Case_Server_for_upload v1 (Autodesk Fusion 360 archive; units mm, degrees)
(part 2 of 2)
joint_origin "JointOrigin1"
derived_base_feature "Derived Base Feature1" bodies "side1", "side2", "Body1"
position "Position11"
joint_origin "JointOrigin1"
as_built_joint "As-built9"
as_built_joint "As-built10"
position "Position12"
as_built_joint "As-built11"
base_feature "Base Feature1"
sketch "Sketch1" plane through (0, 0, 0) normal (0, 0, 1) x axis (1, 0, 0)
  line L1 (-0.425, -0.775) -> (0.425, -0.775)
  line L2 (-0.425, 0.775) -> (-0.425, -0.775)
  line L3 (0.425, 0.775) -> (-0.425, 0.775)
  line L4 (0.425, -0.775) -> (0.425, 0.775)
  line L5 (-0.425, 0) -> (0.425, 0)
  line L6 (-0.425, -0.625) -> (0.425, -0.625)
  line L7 (-0.425, 0.625) -> (0.425, 0.625)
  line L8 (0, -0.625) -> (0, 0.625)
  point P6 (0.425, 0)
  point P7 (-0.425, 0)
  point P8 (0.425, -0.625)
  point P9 (-0.425, -0.625)
  point P10 (0.425, 0.625)
  point P11 (-0.425, 0.625)
  point P12 (0, 0.625)
  point P13 (0, -0.625)
  point P1 (0, 0)
  point P2 (0.425, -0.775)
  point P3 (-0.425, -0.775)
  point P5 (0.425, 0.775)
  horizontal L1
  vertical L2
  horizontal L3
  vertical L4
  midpoint L4 P6
  midpoint L2 P7
  coincident L4 P8
  coincident L2 P9
  perpendicular L2 L6
  coincident L4 P10
  coincident L2 P11
  perpendicular L2 L7
  midpoint L7 P12
  midpoint L6 P13
  coincident P1 L5
  coincident P1 L8
  dimension "d117_1_1" distance P2 P3 = 0.85
  dimension "d118_1_1" distance P2 P5 = 1.55
  dimension "d120_1_1" distance L1 L6 = 0.15
  dimension "d121_1_1" distance L3 L7 = 0.15
extrude "Extrude1" new body sketch "Sketch1" profile of L2 L4 L6 L7 blind 0.45 named "d123_1_1"
extrude "Extrude2" new body sketch "Sketch1" profile of L1 L2 L3 L4 L6 L7 blind 0.45 named "d125_1_1" bodies "side1", "side2"
sketch "Sketch2" plane through (0, 0, 0.45) normal (0, 0, 1) x axis (1, 0, 0)
  dimension "d127_1_1" = 0.5
extrude "Extrude3" add sketch "Sketch2" blind 0.01 named "d128_1_1"
position "Position13"
joint_origin "JointOrigin2"
joint "Assemble8" alignAngle 90 alignOffsetX 6.925 (= "( 25.4 / 2 ) * 1 mm - ( 1.55 / 2 ) * 1 mm - 5 mm") alignOffsetY -6.675 (= "( -26.2 / 2 ) * 1 mm + ( 0.85 / 2 ) * 1 mm + 6 mm") alignOffsetZ 0
sketch "Sketch1" plane through (0, 0, 0) normal (0, 0, 1) x axis (1, 0, 0)
  line L1 (-0.8, -1.45) -> (0.8, -1.45)
  line L2 (-0.8, 1.45) -> (-0.8, -1.45)
  line L3 (0.8, 1.45) -> (-0.8, 1.45)
  line L4 (0.8, -1.45) -> (0.8, 1.45)
  line L5 (-0.8, 1.45) -> (0.8, -1.45)
  line L6 (0.8, 1.45) -> (-0.8, -1.45)
  point P6 (0, 0)
  point P1 (0, 0)
  point P4 (-0.8, 1.45)
  point P5 (0.8, 1.45)
  point P3 (-0.8, -1.45)
  horizontal L1
  perpendicular L1 L2
  parallel L1 L3
  parallel L2 L4
  coincident L5 P6
  coincident L6 P6
  coincident P1 P6
  dimension "d1_1" distance P4 P5 = 1.6
  dimension "d2_1" distance P3 P4 = 2.9
extrude "Extrude1" new body sketch "Sketch1" profile of L1 L2 L3 L4 along normal blind 1.1 named "d3_1"
work_plane "WorkPlane1"
sketch "Sketch2" plane through (0, 0, 0.4) normal (0, -1, 0) x axis (1, 0, 0)
  line L1 (-0.8, 0.7) -> (0.8, 0.7)
  line L2 (0.8, -0.4) -> (-0.8, -0.4)
  line L3 (0, -0.4) -> (0, 0.7)
  line L4 (-0.8, 0.7) -> (-0.8, -0.4)
  line L5 (0.8, 0.7) -> (0.8, -0.4)
  line L6 (0.8, 0.15) -> (-0.8, 0.15)
  line L7 (1.1, 0.4) -> (0.8, 0.4)
  line L8 (1.1, -0.35) -> (1.1, 0.4)
  line L9 (1.4, -0.35) -> (1.1, -0.35)
  line L10 (1.4, -0.5) -> (1.4, -0.35)
  line L11 (0.95, -0.5) -> (1.4, -0.5)
  line L12 (0.95, 0.25) -> (0.95, -0.5)
  line L13 (0.8, 0.25) -> (0.95, 0.25)
  line L14 (0.8, 0.25) -> (0.8, 0.4)
  line L15 (-0.95, -0.5) -> (-1.4, -0.5)
  line L16 (-0.8, 0.25) -> (-0.8, 0.4)
  line L17 (-1.1, 0.4) -> (-0.8, 0.4)
  line L18 (-1.4, -0.5) -> (-1.4, -0.35)
  line L19 (-1.1, -0.35) -> (-1.1, 0.4)
  line L20 (-0.8, 0.25) -> (-0.95, 0.25)
  line L21 (-1.4, -0.35) -> (-1.1, -0.35)
  line L22 (-0.95, 0.25) -> (-0.95, -0.5)
  point P6 (0, 0.7)
  point P7 (0, -0.4)
  point P10 (-0.8, 0.15)
  point P11 (0.8, 0.15)
  point P12 (0.8, 0.4)
  point P19 (0.8, 0.25)
  point P5 (0.8, -0.4)
  point P30 (-0.8, -0.4)
  point P8 (0.8, -0.4)
  point P22 (-0.8, -0.4)
  point P24 (-0.8, 0.15)
  point P26 (-0.8, 0.4)
  point P13 (1.1, 0.4)
  point P20 (-1.1, 0.4)
  point P14 (1.1, -0.35)
  point P21 (-1.1, -0.35)
  point P15 (1.4, -0.35)
  point P25 (-1.4, -0.35)
  point P16 (1.4, -0.5)
  point P23 (-1.4, -0.5)
  point P17 (0.95, -0.5)
  point P27 (-0.95, -0.5)
  point P18 (0.95, 0.25)
  point P29 (-0.95, 0.25)
  point P28 (-0.8, 0.25)
  midpoint L1 P6
  midpoint L2 P7
  midpoint L4 P10
  midpoint L5 P11
  coincident L5 P12
  perpendicular L5 L7
  perpendicular L7 L8
  perpendicular L5 L9
  perpendicular L9 L10
  perpendicular L5 L11
  perpendicular L11 L12
  coincident L5 P19
  perpendicular L5 L13
  symmetric P5 L3 P30
  symmetric L3 P8 P22
  symmetric L3 P11 P24
  symmetric L3 P12 P26
  symmetric L3 P13 P20
  symmetric L3 P14 P21
  symmetric L3 P15 P25
  symmetric L3 P16 P23
  symmetric L3 P17 P27
  symmetric L3 P18 P29
  symmetric L3 P19 P28
  dimension "d5_1" distance L2 L11 = 0.1
  dimension "d8_2" distance P12 P19 = 0.15
  dimension "d9_2" distance L6 L13 = 0.1
  dimension "d10_2" distance L8 L12 = 0.15
  dimension "d11_2" distance P15 P16 = 0.15
  dimension "d13_1" distance L3 L10 = 1.4 (= "( 2.8 / 2 ) * 1 mm")
  dimension "d14_1" distance L8 L10 = 0.3
extrude "Extrude2" new body sketch "Sketch2" profile of L15 L16 L17 L18 L19 L20 L21 L22 distance 0.2 named "d15_1" bodies "leg1"
extrude "Extrude3" new body sketch "Sketch2" profile of L7 L8 L9 L10 L11 L12 L13 L14 distance 0.2 named "d17_1" from offset 0.95 (= "( 1.9 / 2 ) * 1 mm") named "d19_1" bodies "leg2"
extrude "Extrude4" new body sketch "Sketch2" profile of L7 L8 L9 L10 L11 L12 L13 L14 distance 0.2 named "d21_1" from offset -0.95 (= "( -1.9 / 2 ) * 1 mm") named "d20_1" bodies "leg3"
fillet "Fillet1" radius 0.3 named "d24_2" 0.3 named "d26_2" 0.3 named "d28_2" 0.3 named "d30_1" 0.3 named "d32_1" 0.3 named "d34_1" 0.3 named "d36_1" 0.3 named "d38_1" 0.3 named "d40_1" 0.3 named "d42_1" 0.3 named "d44_1" 0.3 named "d46_1"
sketch "Sketch3" plane through (0, 0, 1.1) normal (0, 0, 1) x axis (-1, 0, 0)
  dimension "d47_1" = 0.8
extrude "Extrude5" add sketch "Sketch3" along normal blind 0.01 named "d48_1"
joint "Assemble9" alignAngle 90 alignOffsetX -0.75 (= "( 25.4 / 2 ) * 1 mm - ( 2.9 / 2 ) * 1 mm - 12 mm") alignOffsetY -7.3 (= "( -26.2 / 2 ) * 1 mm + ( 1.6 / 2 ) * 1 mm + 5 mm") alignOffsetZ 0.1
base_feature "Base Feature1"
sketch "Sketch1" plane through (0, 0, 0) normal (0, 0, 1) x axis (1, 0, 0)
  line L1 (-0.425, -0.65) -> (0.425, -0.65)
  line L2 (-0.425, 0.65) -> (-0.425, -0.65)
  line L3 (0.425, 0.65) -> (-0.425, 0.65)
  line L4 (0.425, -0.65) -> (0.425, 0.65)
  line L5 (0.425, 0) -> (-0.425, 0)
  line L6 (0, -0.65) -> (0, 0.65)
  point P6 (-0.425, 0)
  point P7 (0.425, 0)
  point P8 (0, 0.65)
  point P9 (0, -0.65)
  point P1 (0, 0)
  point P2 (0.425, -0.65)
  point P3 (-0.425, -0.65)
  point P5 (0.425, 0.65)
  horizontal L1
  vertical L2
  horizontal L3
  vertical L4
  midpoint L2 P6
  midpoint L4 P7
  midpoint L3 P8
  midpoint L1 P9
  coincident P1 L6
  coincident P1 L5
  dimension "d79" distance P2 P3 = 0.85
  dimension "d80" distance P2 P5 = 1.3 (= "1.6 mm - 0.3 mm")
extrude "Extrude1" new body sketch "Sketch1" profile of L1 L2 L3 L4 blind 0.8
extrude "Extrude2" new body of existing geometry blind 0.15 bodies "side1"
extrude "Extrude3" new body of existing geometry blind 0.15 bodies "side2"
joint "Assemble10" alignAngle 0 alignOffsetX -4 alignOffsetY -7.3 alignOffsetZ 0
work_plane "WorkPlane1" AlongDistance 0.5
sketch "Sketch1" plane through (0, -5.9, 0) normal (0, -1, 0) x axis (1, 0, 0)
  line L1 (12.35, 3.3) -> (12.35, 3.25)
  line L2 (-12.35, 3.3) -> (12.35, 3.3)
  line L3 (-12.35, 3.25) -> (-12.35, 3.3)
  line L4 (12.35, 3.25) -> (-12.35, 3.25)
  line L5 (0, 3.25) -> (0, 3.3)
  line L6 (-4.25, 3.3) -> (4.25, 3.3)
  line L7 (-4.25, 3.25) -> (-4.25, 3.3)
  line L8 (4.25, 3.25) -> (-4.25, 3.25)
  line L9 (4.25, 3.3) -> (4.25, 3.25)
  line L10 (-4.25, 3.25) -> (4.25, 3.3)
  line L11 (4.25, 3.25) -> (-4.25, 3.3)
  point P6 (0, 3.3)
  point P7 (0, 3.25)
  point P12 (0, 3.275)
  point P10 (-4.25, 3.25)
  point P11 (4.25, 3.25)
  midpoint L2 P6
  midpoint L4 P7
  perpendicular L4 L5
  horizontal L6
  perpendicular L6 L7
  parallel L6 L8
  parallel L7 L9
  coincident L10 P12
  coincident L11 P12
  midpoint L5 P12
  collinear L2 L6
  dimension "d196" distance P10 P11 = 8.5
sketch "Sketch2" plane through (0, 0, 2) normal (0, 0, 1) x axis (1, 0, 0)
  line L1 (6.3, -10.6) -> (-6.3, -10.6)
  line L2 (-12.35, -8.4) -> (12.35, -8.4)
  line L3 (0, -8.4) -> (0, -10.6)
  line L4 (-4.25, -12.1) -> (4.25, -12.1)
  line L5 (-4.25, -12.05) -> (-4.25, -12.1)
  line L6 (4.25, -12.05) -> (-4.25, -12.05)
  line L7 (4.25, -12.1) -> (4.25, -12.05)
  line L8 (-4.25, -12.05) -> (4.25, -12.1)
  line L9 (4.25, -12.05) -> (-4.25, -12.1)
  line L10 (12.7, -13.1) -> (7.3, -13.1)
  point P6 (0, -10.6)
  point P7 (0, -8.4)
  point P12 (0, -12.075)
  point P10 (-4.25, -12.05)
  point P11 (4.25, -12.05)
  point P9 (-4.25, -12.1)
  midpoint L1 P6
  midpoint L2 P7
  horizontal L4
  perpendicular L4 L5
  parallel L4 L6
  parallel L5 L7
  coincident L8 P12
  coincident L9 P12
  coincident L3 P12
  dimension "d198" distance P10 P11 = 8.5
  dimension "d199" distance P9 P10 = 0.05
  dimension "d200" distance L4 L10 = 1
work_plane "WorkPlane2" AlongDistance -6 (= "-9 mm + 3 mm")
sketch "Sketch3" plane through (-10, -7.1, 0.75) normal (0, -1, 0) x axis (1, 0, 0)
  line L1 (-2.35, 2.55) -> (22.35, 2.55)
  line L2 (10, 2.55) -> (10, -3.25)
  line L3 (22.7, 0.75) -> (22.7, -0.75)
  line L4 (-2.7, 0.75) -> (-2.7, -0.75)
  line L5 (21, -0.75) -> (-1, -0.75)
  line L6 (21, -0.8) -> (21, -0.75)
  line L7 (-1, -0.8) -> (21, -0.8)
  line L8 (-1, -0.75) -> (-1, -0.8)
  line L9 (21, -0.8) -> (-1, -0.75)
  line L10 (-1, -0.8) -> (21, -0.75)
  line L11 (22.7, -0.75) -> (-2.7, -0.75)
  point P5 (10, 2.55)
  point P10 (10, 2.55)
  point P4 (10, -3.25)
  point P11 (10, -3.25)
  point P16 (10, -0.775)
  point P14 (21, -0.8)
  point P15 (-1, -0.8)
  point P13 (21, -0.75)
  perpendicular L1 L2
  symmetric L2 L3 L4
  coincident P5 P10
  coincident P4 P11
  horizontal L5
  perpendicular L5 L6
  parallel L5 L7
  parallel L6 L8
  coincident L9 P16
  coincident L10 P16
  coincident L2 P16
  collinear L5 L11
  dimension "d202" distance P14 P15 = 22
  dimension "d203" distance P13 P14 = 0.05
work_plane "WorkPlane3"
sketch "Sketch4" plane through (0, -4.1, -0.025) normal (-1, 0, 0) x axis (0, 1, 0)
  line L1 (-1.8, -3.275) -> (-4.3, -3.275)
  line L2 (-6.5, -0.025) -> (-6.5, -1.525)
  line L3 (-5.8, -3.3) -> (-1.8, -3.3)
  line L4 (-9, -0.025) -> (17.2, -0.025)
  line L5 (-6.8, 0) -> (0, 0)
  curve K1 (-6.8, 0) -> (-5.8, -3.3)
  curve K2 (-6.6, -3.3) -> (-5, -3.3)
  curve K3 (-8.05, -1.75) -> (-7.9, -2.3)
  curve K4 (-6.1833, 0) -> (-7.4167, 0)
  point P1 (0, 0)
  point P13 (0, 0)
  point P9 (-1.8, -3.3)
  point P15 (-1.8, -3.3)
  point P6 (-7.975, -2.025)
  point P16 (-7.975, -2.025)
  point P10 (-5.8, -3.3)
  point P14 (-6.8, 0)
  parallel L1 L3
  coincident P1 P13
  parallel L4 L5
  coincident P9 P15
  coincident P6 P16
  midpoint P10 K2
  midpoint P16 K3
  midpoint P14 K4
  dimension "d204" distance P9 P10 = 4
  dimension "d205" distance P13 P14 = 6.8
loft "Loft1" sketch "Sketch1" + "Sketch2" + "Sketch3"
sketch "Sketch3" plane through (0, 0, 1.5) normal (0, 0, 1) x axis (-1, 0, 0)
  line L1 (7.3, 13.1) -> (12.7, 13.1)
  line L2 (7.3, 11.6) -> (7.3, 13.1)
  line L3 (-6.3, 10.6) -> (6.3, 10.6)
  line L4 (-7.3, 13.1) -> (-7.3, 11.6)
  line L5 (-12.7, 13.1) -> (-7.3, 13.1)
  line L6 (-12.7, -13.1) -> (-12.7, 13.1)
  line L7 (12.7, -13.1) -> (-12.7, -13.1)
  line L8 (12.7, 13.1) -> (12.7, -13.1)
  curve K1
  curve K2
  curve K3
  curve K4
  line L9 (0, -9.1) -> (0, -11.1)
  circle C1 centre (-3.81, -11.83) radius 0.6
  circle C2 centre (-1.27, -11.83) radius 0.6
  circle C3 centre (1.27, -11.83) radius 0.6
  circle C4 centre (3.81, -11.83) radius 0.6
  circle C5 centre (10.7, -11.1) radius 1.5
  circle C6 centre (-10.7, -11.1) radius 1.5
  circle C7 centre (10.7, 11.1) radius 1.5
  circle C8 centre (-10.7, 11.1) radius 1.5
  arc A1 centre (6.3, 11.6) radius 1 clockwise from (7.3, 11.6) to (6.3, 10.6)
  arc A2 centre (-6.3, 11.6) radius 1 clockwise from (-6.3, 10.6) to (-7.3, 11.6)
  point P22 (0, -11.1)
  point P23 (0, -9.1)
  coincident P22
  coincident P23
  symmetric L6 L8 L9
  dimension "d209" distance L7 K3 = 2
  dimension "d206" Text1-Height = 0.8
  dimension "d207" distance = 11.5
  dimension "d208" distance = 2
extrude "Extrude5" add sketch "Sketch3" along normal blind 0.01
extrude "Extrude1" add of existing geometry blind 3
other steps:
create_component "CreateComponent1"
create_component "CreateComponent2"
create_component "CreateComponent3"
create_component "CreateComponent4"
create_component "CreateComponent12"
joint_origin "JointOrigin1"
joint_origin "JointOrigin5"
create_component "CreateComponent13"
create_component "CreateComponent14"
joint_origin "JointOrigin2"
joint_origin "JointOrigin7"
create_component "CreateComponent16"
joint_origin "JointOrigin2"
joint_origin "JointOrigin9"
create_component "CreateComponent17"
create_component "CreateComponent18"
joint_origin "JointOrigin2"
joint_origin "JointOrigin12"
joint_origin "JointOrigin3"
joint_origin "JointOrigin14"
create_component "CreateComponent19"
create_component "CreateComponent20"
create_component "CreateComponent21"
create_component "CreateComponent22"
create_component "CreateComponent23"
joint_origin "JointOrigin3"
joint_origin "JointOrigin15"
create_component "CreateComponent24"
joint_origin "JointOrigin1"
joint_origin "JointOrigin16"
create_component "CreateComponent25"
joint_origin "JointOrigin1"
joint_origin "JointOrigin17"
create_component "CreateComponent26"
named bodies: "board_body", "ring2", "ring3", "ring1", "ring4", "pad", "glass1", "glass2", "header1", "pin1", "header2", "header3", "header4", "pin2", "pin3", "pin4 (1)", "ring5", "ring6", "ring7 (1)", "ring7", "solder1", "solder2", "solder3", "solder4", "side1", "side2", "Body1", "leg1", "leg2", "leg3"

design "MicroSD Reader Assembly"
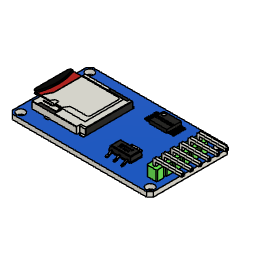
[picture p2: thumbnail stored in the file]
description: Part Number
part number: MicroSD Reader Assembly
part number: sdreader
part number: AMS1117
part number: card sd
base_feature "Base Feature1"
base_feature "Base Feature1"
base_feature "Base Feature1"
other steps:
create_component "CreateComponent1"
create_component "CreateComponent2"
create_component "CreateComponent3"

design "Control" references "DB_Updated", "Button_Board_II", "1.3+Inch+OLED+Display", "MicroSD Reader Assembly"
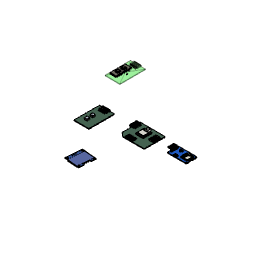
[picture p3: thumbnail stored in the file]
parameter "Base_extrusion" = 2
parameter "button_extrusion" = 4
parameter "cutter" = 1
base_mesh_feature "Base Mesh Feature"
sketch "Sketch1" plane through (0, 0, 0) normal (0, 0, 1) x axis (1, 0, 0)
  line L1 (5, 10) -> (-10, 10)
  line L2 (5, -25) -> (5, 10)
  line L3 (-10, -25) -> (5, -25)
  line L4 (-10, 10) -> (-10, -25)
  line L5 (-0.5549, -0.8) -> (-5, -0.8)
  line L6 (-2.7475, -3.1654) -> (-2.7475, 1.3967)
  line L7 (-4.495, -3.5) -> (-1, -3.5)
  line L8 (-5.495, 0.9) -> (-5.495, -2.5)
  line L9 (-1, 1.9) -> (-4.495, 1.9)
  line L10 (0, -2.5) -> (0, 0.9)
  line L11 (-5.495, 1.9) -> (0, -3.5)
  line L12 (0, 1.9) -> (-5.495, -3.5)
  line L13 (-2.7262, -15.3) -> (-2.7262, -10.8381)
  line L14 (-0.5, -13.0424) -> (-4.9528, -13.0424)
  line L15 (-2.7264, -13.0424) -> (-2.7475, -0.8)
  line L16 (7.263, -6.9039) -> (-2.7369, -6.9212)
  line L17 (-0.9696, -15.7363) -> (-4.4646, -15.7484)
  line L18 (-5.468, -14.7518) -> (-5.4797, -11.3519)
  line L19 (-4.4832, -10.3484) -> (-0.9882, -10.3363)
  line L20 (0.0152, -11.3329) -> (0.027, -14.7329)
  line L21 (1, -2.5) -> (1, 0.9)
  line L22 (-4.495, -4.5) -> (-1, -4.5)
  line L23 (-6.495, 0.9) -> (-6.495, -2.5)
  line L24 (-1, 2.9) -> (-4.495, 2.9)
  line L25 (-4.4867, -9.3484) -> (-0.9917, -9.3364)
  line L26 (-6.468, -14.7553) -> (-6.4797, -11.3553)
  line L27 (-0.9661, -16.7363) -> (-4.4611, -16.7484)
  line L28 (1.0152, -11.3294) -> (1.027, -14.7294)
  arc A1 centre (-4.495, 0.9) radius 1 clockwise from (-5.495, 0.9) to (-4.495, 1.9)
  arc A2 centre (-1, 0.9) radius 1 clockwise from (-1, 1.9) to (0, 0.9)
  arc A3 centre (-1, -2.5) radius 1 clockwise from (0, -2.5) to (-1, -3.5)
  arc A4 centre (-4.495, -2.5) radius 1 clockwise from (-4.495, -3.5) to (-5.495, -2.5)
  arc A5 centre (-4.4798, -11.3484) radius 1 clockwise from (-5.4797, -11.3519) to (-4.4832, -10.3484)
  arc A6 centre (-4.468, -14.7484) radius 1 clockwise from (-4.4646, -15.7484) to (-5.468, -14.7518)
  arc A7 centre (-0.973, -14.7363) radius 1 clockwise from (0.027, -14.7329) to (-0.9696, -15.7363)
  arc A8 centre (-0.9848, -11.3363) radius 1 clockwise from (-0.9882, -10.3363) to (0.0152, -11.3329)
  arc A9 centre (-1, -2.5) radius 2 clockwise from (1, -2.5) to (-1, -4.5)
  arc A10 centre (-4.495, -2.5) radius 2 clockwise from (-4.495, -4.5) to (-6.495, -2.5)
  arc A11 centre (-4.495, 0.9) radius 2 clockwise from (-6.495, 0.9) to (-4.495, 2.9)
  arc A12 centre (-1, 0.9) radius 2 clockwise from (-1, 2.9) to (1, 0.9)
  arc A13 centre (-4.4798, -11.3484) radius 2 clockwise from (-6.4797, -11.3553) to (-4.4867, -9.3484)
  arc A14 centre (-4.468, -14.7484) radius 2 clockwise from (-4.4611, -16.7484) to (-6.468, -14.7553)
  arc A15 centre (-0.973, -14.7363) radius 2 clockwise from (1.027, -14.7294) to (-0.9661, -16.7363)
  arc A16 centre (-0.9848, -11.3363) radius 2 clockwise from (-0.9917, -9.3364) to (1.0152, -11.3294)
  point P14 (-2.7475, -0.8)
  point P19 (-2.7475, -0.8)
  point P20 (-2.7264, -13.0424)
  point P21 (-2.7369, -6.9212)
  point P12 (-5.495, 1.9)
  point P13 (0, 1.9)
  point P10 (0, -3.5)
  point P11 (-5.495, -3.5)
  point P22 (7.263, -6.9039)
  horizontal L1
  perpendicular L1 L2
  perpendicular L2 L3
  perpendicular L1 L4
  horizontal L5
  perpendicular L5 L6
  horizontal L7
  perpendicular L7 L8
  parallel L7 L9
  parallel L8 L10
  coincident L11 P14
  coincident L12 P14
  coincident L5 P14
  coincident L6 P14
  vertical L13
  horizontal L14
  coincident P14 P19
  midpoint L14 P20
  midpoint L15 P21
  coincident P12 L8
  coincident P12 L9
  tangent L8 A1
  tangent L9 A1
  coincident P13 L9
  coincident P13 L10
  tangent L9 A2
  tangent L10 A2
  equal A1 A2
  coincident P10 L7
  coincident P10 L10
  tangent L7 A3
  tangent L10 A3
  equal A1 A3
  coincident P11 L7
  coincident P11 L8
  tangent L7 A4
  tangent L8 A4
  equal A1 A4
  tangent L19 A5
  tangent L18 A5
  equal A1 A5
  tangent L17 A6
  tangent L18 A6
  equal A1 A6
  tangent L17 A7
  tangent L20 A7
  equal A1 A7
  tangent L19 A8
  tangent L20 A8
  dimension "d14" angle L15 L16 = 90
  dimension "d15" distance P21 P22 = 10
  dimension "d18" radius A1 = 1
  dimension "d19" radius A8 = 1
  dimension "d22" distance A3 = 1
  dimension "d23" = 1
extrude "Extrude1" new body sketch "Sketch1" profile of L1 L2 L3 L4 L7 L8 L9 L10 L17 L18 L19 L20 A1 A2 A3 A4 A5 A6 A7 A8 L21 L22 L24 A12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 along normal blind 2 (= "Base_extrusion") taper -5 bodies "Base"
mesh_repair "MeshRepair1"
extrude "Extrude3" new body sketch "Sketch1" profile of L7 L8 L9 L10 L17 L18 L19 L20 A1 A2 A3 A4 A5 A6 A7 A8 A9 along normal blind 4 (= "button_extrusion") taper -5 bodies "Button_superior", "Button_inferior"
fillet "Fillet1" radius 0.5
fillet "Fillet2" radius 0.4
sketch "Sketch9" plane through (0, 0, 0) normal (1, 0, 0) x axis (0, 1, 0)
sketch "Sketch10" plane through (0, 0, 2) normal (0, 0, 1) x axis (-1, 0, 0)
  line L1 (9.825, 24.825) -> (9.825, -9.825)
  line L2 (-4.825, 24.825) -> (9.825, 24.825)
  line L3 (-4.825, -9.825) -> (-4.825, 24.825)
  line L4 (9.825, -9.825) -> (-4.825, -9.825)
  line L5 (1, 3.325) -> (4.495, 3.325)
  line L6 (0.175, -0.9) -> (0.175, 2.5)
  line L7 (4.495, -1.725) -> (1, -1.725)
  line L8 (5.32, 2.5) -> (5.32, -0.9)
  line L9 (0.1597, 11.3335) -> (0.148, 14.7335)
  line L10 (4.4826, 10.5234) -> (0.9876, 10.5113)
  line L11 (5.293, 14.7512) -> (5.3048, 11.3513)
  line L12 (0.9702, 15.5613) -> (4.4652, 15.5734)
  line L13 (6.293, 14.7547) -> (6.3048, 11.3547)
  line L14 (0.9667, 16.5613) -> (4.4617, 16.5734)
  line L15 (-0.8403, 11.33) -> (-0.852, 14.73)
  line L16 (4.486, 9.5234) -> (0.991, 9.5113)
  line L17 (4.495, -2.725) -> (1, -2.725)
  line L18 (6.32, 2.5) -> (6.32, -0.9)
  line L19 (1, 4.325) -> (4.495, 4.325)
  line L20 (-0.825, -0.9) -> (-0.825, 2.5)
  arc A1 centre (4.495, 2.5) radius 0.825 clockwise from (4.495, 3.325) to (5.32, 2.5)
  arc A2 centre (1, 2.5) radius 0.825 clockwise from (0.175, 2.5) to (1, 3.325)
  arc A3 centre (1, -0.9) radius 0.825 clockwise from (1, -1.725) to (0.175, -0.9)
  arc A4 centre (4.495, -0.9) radius 0.825 clockwise from (5.32, -0.9) to (4.495, -1.725)
  arc A5 centre (0.9848, 11.3363) radius 0.825 clockwise from (0.9876, 10.5113) to (0.1597, 11.3335)
  arc A6 centre (4.4798, 11.3484) radius 0.825 clockwise from (5.3048, 11.3513) to (4.4826, 10.5234)
  arc A7 centre (4.468, 14.7484) radius 0.825 clockwise from (4.4652, 15.5734) to (5.293, 14.7512)
  arc A8 centre (0.973, 14.7363) radius 0.825 clockwise from (0.148, 14.7335) to (0.9702, 15.5613)
  arc A9 centre (4.468, 14.7484) radius 1.825 clockwise from (4.4617, 16.5734) to (6.293, 14.7547)
  arc A10 centre (0.973, 14.7363) radius 1.825 clockwise from (-0.852, 14.73) to (0.9667, 16.5613)
  arc A11 centre (0.9848, 11.3363) radius 1.825 clockwise from (0.991, 9.5113) to (-0.8403, 11.33)
  arc A12 centre (4.4798, 11.3484) radius 1.825 clockwise from (6.3048, 11.3547) to (4.486, 9.5234)
  arc A13 centre (4.495, -0.9) radius 1.825 clockwise from (6.32, -0.9) to (4.495, -2.725)
  arc A14 centre (4.495, 2.5) radius 1.825 clockwise from (4.495, 4.325) to (6.32, 2.5)
  arc A15 centre (1, 2.5) radius 1.825 clockwise from (-0.825, 2.5) to (1, 4.325)
  arc A16 centre (1, -0.9) radius 1.825 clockwise from (1, -2.725) to (-0.825, -0.9)
  dimension "d33" = 1
  dimension "d34" = 1
extrude "Extrude6" cut sketch "Sketch10" profile of A1 L5 A2 L6 A3 L7 A4 L8 L9 A5 L10 A6 L11 A7 L12 A8 L14 A10 A9 L13 L16 L15 A11 A12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 against normal blind 1.9 taper -5
fillet "Fillet8" radius 0.43
fillet "Fillet9" radius 0.43
fillet "Fillet10" radius 1
fillet "Fillet11" radius 1
sketch "Wax_Block" plane through (0, 0, 0) normal (0, 0, 1) x axis (1, 0, 0)
  line L1 (15, 22) -> (-20, 22)
  line L2 (15, -68) -> (15, 22)
  line L3 (-20, -68) -> (15, -68)
  line L4 (-20, 22) -> (-20, -68)
  line L5 (-10, -25) -> (5, -25)
  line L6 (-10, 10) -> (-10, -25)
  line L7 (5, 10) -> (-10, 10)
  line L8 (5, -25) -> (5, 10)
  line L9 (7, -27) -> (7, 12)
  line L10 (-12, -27) -> (7, -27)
  line L11 (-12, 12) -> (-12, -27)
  line L12 (7, 12) -> (-12, 12)
  point P2 (-20, 22)
  point P3 (15, 22)
  point P5 (-20, -68)
  horizontal L1
  vertical L2
  horizontal L3
  vertical L4
  dimension "d55" distance P2 P3 = 35
  dimension "d56" distance P2 P5 = 90
  dimension "d63" = -2
fillet "Fillet12" radius 1
extrude "Extrude1" new body sketch "Wax_Block" profile of L1 L2 L3 L4 along normal blind 20 bodies "Wax_Block_Mold"
combine "Combine1"
extrude "Extrude2" add sketch "Wax_Block" profile of L1 L2 L3 L4 L11 L9 L10 L12 against normal blind 1
move "Move1"
move "Move2"
move "Move3"
move "Move4"
move "Move5"
position "Position1"
sketch "Sketch21" plane through (0, 0, 0) normal (0, 1, 0) x axis (1, 0, 0)
combine "Combine1" bodies "Base"
sketch "Sketch1" plane through (0, 0, 0) normal (0, 0, 1) x axis (1, 0, 0)
  line L1 (-4.495, -5.2382) -> (-1, -5.2382)
  curve K1 (-4.495, -5.2382) -> (-7.2332, -2.5)
  line L2 (-7.2332, 0.9) -> (-7.2332, -2.5)
  curve K2 (-7.2332, 0.9) -> (-4.495, 3.6382)
  line L3 (-1, 3.6382) -> (-4.495, 3.6382)
  curve K3 (-1, 3.6382) -> (1.7382, 0.9)
  line L4 (1.7382, -2.5) -> (1.7382, 0.9)
  curve K4 (1.7382, -2.5) -> (-1, -5.2382)
  line L5 (-4.4586, -17.4866) -> (-0.9636, -17.4745)
  curve K5 (-4.4586, -17.4866) -> (-7.2062, -14.7578)
  line L6 (-7.2179, -11.3579) -> (-7.2062, -14.7578)
  curve K6 (-7.2179, -11.3579) -> (-4.4892, -8.6102)
  line L7 (-0.9942, -8.5982) -> (-4.4892, -8.6102)
  curve K7 (-0.9942, -8.5982) -> (1.7534, -11.3269)
  line L8 (1.7652, -14.7269) -> (1.7534, -11.3269)
  curve K8 (1.7652, -14.7269) -> (-0.9636, -17.4745)
  line L9 (-8.9087, 8.9087) -> (3.9087, 8.9087)
  line L10 (-8.9087, -23.9087) -> (-8.9087, 8.9087)
  line L11 (3.9087, -23.9087) -> (-8.9087, -23.9087)
  line L12 (3.9087, 8.9087) -> (3.9087, -23.9087)
extrude "Extrude1" new body of existing geometry blind 2
move "Move1"
move "Move2"
component_insert "Component Insert1"
component_insert "Component Insert2"
component_insert "Component Insert3"
component_insert "Component Insert4"
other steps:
create_component "CreateComponent3"
create_component "CreateComponent4"
create_component "CreateComponent5"
create_component "CreateComponent6"
named bodies: "Base", "Button_superior", "Button_inferior", "Wax_Block_Mold"

design "1.3+Inch+OLED+Display"
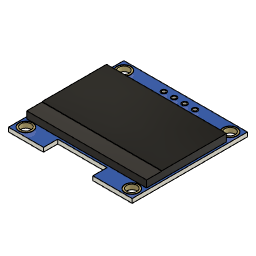
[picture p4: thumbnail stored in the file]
box_primitive "BoxPrimitive1" DistanceX 33.2 DistanceY 35.6 DistanceZ 1.2 OffsetDistanceX 0 OffsetDistanceY 0
sketch "Sketch2" plane through (0, 1.2, 0) normal (0, 1, 0) x axis (-1, 0, 0)
  line L1 (-35.6, 33.2) -> (0, 33.2)
  line L2 (-35.6, 0) -> (-35.6, 33.2)
  line L3 (0, 0) -> (-35.6, 0)
  line L4 (0, 33.2) -> (0, 0)
  line L5 (-24.2659, 33.2) -> (-10.0659, 33.2)
  line L6 (-24.2659, 29.1) -> (-24.2659, 33.2)
  line L7 (-10.0659, 29.1) -> (-24.2659, 29.1)
  line L8 (-10.0659, 33.2) -> (-10.0659, 29.1)
  point P6 (-10.0659, 33.2)
  point P7 (-24.2659, 33.2)
  point P9 (-10.0659, 29.1)
  horizontal L5
  vertical L6
  horizontal L7
  vertical L8
  coincident L1 P6
  dimension "d7" distance P6 P7 = 14.2
  dimension "d8" distance P6 P9 = 4.1
extrude "Extrude1" cut sketch "Sketch2" profile of L1 L5 L6 L7 L8 against normal blind 7
sketch "Sketch3" plane through (0, 1.2, 0) normal (0, 1, 0) x axis (-1, 0, 0)
  line L1 (-10.0659, 29.1) -> (-10.0659, 33.2)
  line L2 (-24.2659, 29.1) -> (-10.0659, 29.1)
  line L3 (-24.2659, 33.2) -> (-24.2659, 29.1)
  line L4 (-35.6, 33.2) -> (-24.2659, 33.2)
  line L5 (-35.6, 0) -> (-35.6, 33.2)
  line L6 (0, 0) -> (-35.6, 0)
  line L7 (0, 33.2) -> (0, 0)
  line L8 (-10.0659, 33.2) -> (0, 33.2)
  line L9 (-35.1, 22.762) -> (-35.6, 22.762)
  line L10 (-0.5394, 28.5002) -> (-35.0394, 28.5002)
  line L11 (-0.5394, 5.5002) -> (-0.5394, 28.5002)
  line L12 (-35.0394, 5.5002) -> (-0.5394, 5.5002)
  line L13 (-35.0394, 28.5002) -> (-35.0394, 5.5002)
  point P10 (-35.6, 22.762)
  point P11 (-35.1, 22.762)
  point P12 (-35.0394, 28.5002)
  point P13 (-0.5394, 28.5002)
  point P15 (-35.0394, 5.5002)
  coincident L5 P10
  perpendicular L5 L9
  horizontal L10
  vertical L11
  horizontal L12
  vertical L13
  dimension "d12" distance P10 P11 = 0.5
  dimension "d13" distance P12 P13 = 34.5
  dimension "d14" distance P12 P15 = 23
extrude "Extrude2" add sketch "Sketch3" profile of L10 L11 L12 L13 along normal blind 2.1
sketch "Sketch4" plane through (0, 1.2, 0) normal (0, 1, 0) x axis (-1, 0, 0)
  line L1 (-35.0394, 28.5002) -> (-35.0394, 5.5002)
  line L2 (-0.5394, 28.5002) -> (-35.0394, 28.5002)
  line L3 (-0.5394, 5.5002) -> (-0.5394, 28.5002)
  line L4 (-35.0394, 5.5002) -> (-0.5394, 5.5002)
  line L5 (-10.0659, 29.1) -> (-10.0659, 33.2)
  line L6 (-24.2659, 29.1) -> (-10.0659, 29.1)
  line L7 (-24.2659, 33.2) -> (-24.2659, 29.1)
  line L8 (-35.6, 33.2) -> (-24.2659, 33.2)
  line L9 (-35.6, 0) -> (-35.6, 33.2)
  line L10 (0, 0) -> (-35.6, 0)
  line L11 (0, 33.2) -> (0, 0)
  line L12 (-10.0659, 33.2) -> (0, 33.2)
  circle C1 centre (-2.5, 2.5) radius 1.5
  dimension "d17" diameter C1 = 3
extrude "Extrude3" cut sketch "Sketch4" profile of C1 against normal blind 12
sketch "Sketch5" plane through (0, 1.2, 0) normal (0, 1, 0) x axis (-1, 0, 0)
  line L1 (-35.0394, 28.5002) -> (-35.0394, 5.5002)
  line L2 (-0.5394, 28.5002) -> (-35.0394, 28.5002)
  line L3 (-0.5394, 5.5002) -> (-0.5394, 28.5002)
  line L4 (-35.0394, 5.5002) -> (-0.5394, 5.5002)
  line L5 (-10.0659, 29.1) -> (-10.0659, 33.2)
  line L6 (-24.2659, 29.1) -> (-10.0659, 29.1)
  line L7 (-24.2659, 33.2) -> (-24.2659, 29.1)
  line L8 (-35.6, 33.2) -> (-24.2659, 33.2)
  line L9 (-35.6, 0) -> (-35.6, 33.2)
  line L10 (0, 0) -> (-35.6, 0)
  line L11 (0, 33.2) -> (0, 0)
  line L12 (-10.0659, 33.2) -> (0, 33.2)
  circle C1 centre (-2.5, 2.5) radius 1.5
  circle C2 centre (-33.1, 2.5) radius 1.5
  dimension "d20" diameter C2 = 3
extrude "Extrude4" cut sketch "Sketch5" profile of C2 against normal blind 5
sketch "Sketch6" plane through (0, 1.2, 0) normal (0, 1, 0) x axis (-1, 0, 0)
  line L1 (-35.0394, 28.5002) -> (-35.0394, 5.5002)
  line L2 (-0.5394, 28.5002) -> (-35.0394, 28.5002)
  line L3 (-0.5394, 5.5002) -> (-0.5394, 28.5002)
  line L4 (-35.0394, 5.5002) -> (-0.5394, 5.5002)
  line L5 (-10.0659, 29.1) -> (-10.0659, 33.2)
  line L6 (-24.2659, 29.1) -> (-10.0659, 29.1)
  line L7 (-24.2659, 33.2) -> (-24.2659, 29.1)
  line L8 (-35.6, 33.2) -> (-24.2659, 33.2)
  line L9 (-35.6, 0) -> (-35.6, 33.2)
  line L10 (0, 0) -> (-35.6, 0)
  line L11 (0, 33.2) -> (0, 0)
  line L12 (-10.0659, 33.2) -> (0, 33.2)
  circle C1 centre (-33.1, 2.5) radius 1.5
  circle C2 centre (-2.5, 2.5) radius 1.5
  circle C3 centre (-2.5, 30.7) radius 1.5
  dimension "d23" diameter C3 = 3
extrude "Extrude5" cut sketch "Sketch6" profile of C3 against normal blind 2.6
sketch "Sketch7" plane through (0, 1.2, 0) normal (0, 1, 0) x axis (-1, 0, 0)
  line L1 (-35.0394, 28.5002) -> (-35.0394, 5.5002)
  line L2 (-0.5394, 28.5002) -> (-35.0394, 28.5002)
  line L3 (-0.5394, 5.5002) -> (-0.5394, 28.5002)
  line L4 (-35.0394, 5.5002) -> (-0.5394, 5.5002)
  line L5 (-10.0659, 29.1) -> (-10.0659, 33.2)
  line L6 (-24.2659, 29.1) -> (-10.0659, 29.1)
  line L7 (-24.2659, 33.2) -> (-24.2659, 29.1)
  line L8 (-35.6, 33.2) -> (-24.2659, 33.2)
  line L9 (-35.6, 0) -> (-35.6, 33.2)
  line L10 (0, 0) -> (-35.6, 0)
  line L11 (0, 33.2) -> (0, 0)
  line L12 (-10.0659, 33.2) -> (0, 33.2)
  circle C1 centre (-2.5, 30.7) radius 1.5
  circle C2 centre (-33.1, 2.5) radius 1.5
  circle C3 centre (-2.5, 2.5) radius 1.5
  circle C4 centre (-33.1, 30.8) radius 1.5
  dimension "d26" diameter C4 = 3
extrude "Extrude6" cut sketch "Sketch7" profile of C4 against normal blind 6
sketch "Sketch8" plane through (0, 1.2, 0) normal (0, 1, 0) x axis (-1, 0, 0)
  line L1 (-35.0394, 28.5002) -> (-35.0394, 5.5002)
  line L2 (-0.5394, 28.5002) -> (-35.0394, 28.5002)
  line L3 (-0.5394, 5.5002) -> (-0.5394, 28.5002)
  line L4 (-35.0394, 5.5002) -> (-0.5394, 5.5002)
  line L5 (-10.0659, 29.1) -> (-10.0659, 33.2)
  line L6 (-24.2659, 29.1) -> (-10.0659, 29.1)
  line L7 (-24.2659, 33.2) -> (-24.2659, 29.1)
  line L8 (-35.6, 33.2) -> (-24.2659, 33.2)
  line L9 (-35.6, 0) -> (-35.6, 33.2)
  line L10 (0, 0) -> (-35.6, 0)
  line L11 (0, 33.2) -> (0, 0)
  line L12 (-10.0659, 33.2) -> (0, 33.2)
  circle C1 centre (-33.1, 30.8) radius 1.5
  circle C2 centre (-2.5, 30.7) radius 1.5
  circle C3 centre (-33.1, 2.5) radius 1.5
  circle C4 centre (-2.5, 2.5) radius 1.5
  circle C5 centre (-2.5, 2.5) radius 2
  concentric C4 C5
  dimension "d29" diameter C5 = 4
extrude "Extrude7" add sketch "Sketch8" profile of C4 C5 along normal blind 0.1
sketch "Sketch9" plane through (0, 1.2, 0) normal (0, 1, 0) x axis (-1, 0, 0)
  line L1 (-35.0394, 28.5002) -> (-35.0394, 5.5002)
  line L2 (-0.5394, 28.5002) -> (-35.0394, 28.5002)
  line L3 (-0.5394, 5.5002) -> (-0.5394, 28.5002)
  line L4 (-35.0394, 5.5002) -> (-0.5394, 5.5002)
  line L5 (-10.0659, 29.1) -> (-10.0659, 33.2)
  line L6 (-24.2659, 29.1) -> (-10.0659, 29.1)
  line L7 (-24.2659, 33.2) -> (-24.2659, 29.1)
  line L8 (-35.6, 33.2) -> (-24.2659, 33.2)
  line L9 (-35.6, 0) -> (-35.6, 33.2)
  line L10 (0, 0) -> (-35.6, 0)
  line L11 (0, 33.2) -> (0, 0)
  line L12 (-10.0659, 33.2) -> (0, 33.2)
  circle C1 centre (-2.5, 2.5) radius 2
  circle C2 centre (-33.1, 30.8) radius 1.5
  circle C3 centre (-2.5, 30.7) radius 1.5
  circle C4 centre (-33.1, 2.5) radius 1.5
  circle C5 centre (-33.1, 2.5) radius 2
  concentric C4 C5
  dimension "d32" diameter C5 = 4
extrude "Extrude8" add sketch "Sketch9" profile of C4 C5 along normal blind 0.1
sketch "Sketch10" plane through (0, 1.2, 0) normal (0, 1, 0) x axis (-1, 0, 0)
  line L1 (-35.0394, 28.5002) -> (-35.0394, 5.5002)
  line L2 (-0.5394, 28.5002) -> (-35.0394, 28.5002)
  line L3 (-0.5394, 5.5002) -> (-0.5394, 28.5002)
  line L4 (-35.0394, 5.5002) -> (-0.5394, 5.5002)
  line L5 (-10.0659, 29.1) -> (-10.0659, 33.2)
  line L6 (-24.2659, 29.1) -> (-10.0659, 29.1)
  line L7 (-24.2659, 33.2) -> (-24.2659, 29.1)
  line L8 (-35.6, 33.2) -> (-24.2659, 33.2)
  line L9 (-35.6, 0) -> (-35.6, 33.2)
  line L10 (0, 0) -> (-35.6, 0)
  line L11 (0, 33.2) -> (0, 0)
  line L12 (-10.0659, 33.2) -> (0, 33.2)
  circle C1 centre (-33.1, 2.5) radius 2
  circle C2 centre (-2.5, 2.5) radius 2
  circle C3 centre (-33.1, 30.8) radius 1.5
  circle C4 centre (-2.5, 30.7) radius 1.5
  circle C5 centre (-33.1, 30.8) radius 2
  concentric C3 C5
  dimension "d35" diameter C5 = 4
extrude "Extrude9" add sketch "Sketch10" profile of C3 C5 along normal blind 0.1
sketch "Sketch11" plane through (0, 1.2, 0) normal (0, 1, 0) x axis (-1, 0, 0)
  line L1 (-35.0394, 28.5002) -> (-35.0394, 5.5002)
  line L2 (-0.5394, 28.5002) -> (-35.0394, 28.5002)
  line L3 (-0.5394, 5.5002) -> (-0.5394, 28.5002)
  line L4 (-35.0394, 5.5002) -> (-0.5394, 5.5002)
  line L5 (-10.0659, 29.1) -> (-10.0659, 33.2)
  line L6 (-24.2659, 29.1) -> (-10.0659, 29.1)
  line L7 (-24.2659, 33.2) -> (-24.2659, 29.1)
  line L8 (-35.6, 33.2) -> (-24.2659, 33.2)
  line L9 (-35.6, 0) -> (-35.6, 33.2)
  line L10 (0, 0) -> (-35.6, 0)
  line L11 (0, 33.2) -> (0, 0)
  line L12 (-10.0659, 33.2) -> (0, 33.2)
  circle C1 centre (-33.1, 30.8) radius 2
  circle C2 centre (-33.1, 2.5) radius 2
  circle C3 centre (-2.5, 2.5) radius 2
  circle C4 centre (-2.5, 30.7) radius 1.5
  circle C5 centre (-2.5, 30.7) radius 2
  concentric C4 C5
  dimension "d38" diameter C5 = 4
extrude "Extrude10" add sketch "Sketch11" profile of C4 C5 along normal blind 0.1
sketch "Sketch12" plane through (0, 0, 0) normal (0, -1, 0) x axis (1, 0, 0)
  line L1 (24.2659, 29.1) -> (24.2659, 33.2)
  line L2 (10.0659, 29.1) -> (24.2659, 29.1)
  line L3 (10.0659, 33.2) -> (10.0659, 29.1)
  line L4 (0, 33.2) -> (10.0659, 33.2)
  line L5 (0, 0) -> (0, 33.2)
  line L6 (35.6, 0) -> (0, 0)
  line L7 (35.6, 33.2) -> (35.6, 0)
  line L8 (24.2659, 33.2) -> (35.6, 33.2)
  circle C1 centre (33.1, 30.8) radius 1.5
  circle C2 centre (2.5, 30.7) radius 1.5
  circle C3 centre (33.1, 2.5) radius 1.5
  circle C4 centre (2.5, 2.5) radius 1.5
  circle C5 centre (33.1, 30.8) radius 2
  concentric C1 C5
  dimension "d41" diameter C5 = 4
extrude "Extrude11" add sketch "Sketch12" profile of C1 C5 along normal blind 0.1
sketch "Sketch13" plane through (0, 0, 0) normal (0, -1, 0) x axis (1, 0, 0)
  line L1 (24.2659, 29.1) -> (24.2659, 33.2)
  line L2 (10.0659, 29.1) -> (24.2659, 29.1)
  line L3 (10.0659, 33.2) -> (10.0659, 29.1)
  line L4 (0, 33.2) -> (10.0659, 33.2)
  line L5 (0, 0) -> (0, 33.2)
  line L6 (35.6, 0) -> (0, 0)
  line L7 (35.6, 33.2) -> (35.6, 0)
  line L8 (24.2659, 33.2) -> (35.6, 33.2)
  circle C1 centre (33.1, 30.8) radius 2
  circle C2 centre (2.5, 30.7) radius 1.5
  circle C3 centre (33.1, 2.5) radius 1.5
  circle C4 centre (2.5, 2.5) radius 1.5
  circle C5 centre (33.1, 2.5) radius 2
  concentric C3 C5
  dimension "d44" diameter C5 = 4
extrude "Extrude12" add sketch "Sketch13" profile of C3 C5 along normal blind 0.1
sketch "Sketch14" plane through (0, 0, 0) normal (0, -1, 0) x axis (1, 0, 0)
  line L1 (24.2659, 29.1) -> (24.2659, 33.2)
  line L2 (10.0659, 29.1) -> (24.2659, 29.1)
  line L3 (10.0659, 33.2) -> (10.0659, 29.1)
  line L4 (0, 33.2) -> (10.0659, 33.2)
  line L5 (0, 0) -> (0, 33.2)
  line L6 (35.6, 0) -> (0, 0)
  line L7 (35.6, 33.2) -> (35.6, 0)
  line L8 (24.2659, 33.2) -> (35.6, 33.2)
  circle C1 centre (33.1, 2.5) radius 2
  circle C2 centre (33.1, 30.8) radius 2
  circle C3 centre (2.5, 30.7) radius 1.5
  circle C4 centre (2.5, 2.5) radius 1.5
  circle C5 centre (2.5, 2.5) radius 2
  concentric C4 C5
  dimension "d47" diameter C5 = 4
extrude "Extrude13" add sketch "Sketch14" profile of C4 C5 along normal blind 0.1
sketch "Sketch15" plane through (0, 0, 0) normal (0, -1, 0) x axis (1, 0, 0)
  line L1 (24.2659, 29.1) -> (24.2659, 33.2)
  line L2 (10.0659, 29.1) -> (24.2659, 29.1)
  line L3 (10.0659, 33.2) -> (10.0659, 29.1)
  line L4 (0, 33.2) -> (10.0659, 33.2)
  line L5 (0, 0) -> (0, 33.2)
  line L6 (35.6, 0) -> (0, 0)
  line L7 (35.6, 33.2) -> (35.6, 0)
  line L8 (24.2659, 33.2) -> (35.6, 33.2)
  circle C1 centre (2.5, 2.5) radius 2
  circle C2 centre (33.1, 2.5) radius 2
  circle C3 centre (33.1, 30.8) radius 2
  circle C4 centre (2.5, 30.7) radius 1.5
  circle C5 centre (2.5, 30.7) radius 2
  concentric C4 C5
  dimension "d50" diameter C5 = 4
extrude "Extrude14" add sketch "Sketch15" profile of C4 C5 along normal blind 0.1
sketch "Sketch16" plane through (0, 1.2, 0) normal (0, 1, 0) x axis (-1, 0, 0)
  line L1 (-35.0394, 28.5002) -> (-35.0394, 5.5002)
  line L2 (-0.5394, 28.5002) -> (-35.0394, 28.5002)
  line L3 (-0.5394, 5.5002) -> (-0.5394, 28.5002)
  line L4 (-35.0394, 5.5002) -> (-0.5394, 5.5002)
  line L5 (-10.0659, 29.1) -> (-10.0659, 33.2)
  line L6 (-24.2659, 29.1) -> (-10.0659, 29.1)
  line L7 (-24.2659, 33.2) -> (-24.2659, 29.1)
  line L8 (-35.6, 33.2) -> (-24.2659, 33.2)
  line L9 (-35.6, 0) -> (-35.6, 33.2)
  line L10 (0, 0) -> (-35.6, 0)
  line L11 (0, 33.2) -> (0, 0)
  line L12 (-10.0659, 33.2) -> (0, 33.2)
  circle C1 centre (-2.5, 30.7) radius 2
  circle C2 centre (-33.1, 30.8) radius 2
  circle C3 centre (-33.1, 2.5) radius 2
  circle C4 centre (-2.5, 2.5) radius 2
  circle C5 centre (-16.5, 2) radius 0.5
  circle C6 centre (-19.5, 2) radius 0.5
  circle C7 centre (-13.5, 2) radius 0.5
  circle C8 centre (-22.5, 2) radius 0.5
  point P18 (-16.5, 2)
  point P20 (-13.5, 2)
  point P19 (-19.5, 2)
  point P21 (-22.5, 2)
  dimension "d55" diameter C5 = 1
  dimension "d56" diameter C6 = 1
  dimension "d57" distance P18 P20 = 3
  dimension "d58" diameter C7 = 1
  dimension "d59" distance P19 P21 = 3
  dimension "d60" diameter C8 = 1
extrude "Extrude15" cut sketch "Sketch16" profile of C5 C6 C7 C8 against normal blind 2.7
sketch "Sketch17" plane through (0, 1.2, 0) normal (0, 1, 0) x axis (-1, 0, 0)
  line L1 (-35.0394, 28.5002) -> (-35.0394, 5.5002)
  line L2 (-0.5394, 28.5002) -> (-35.0394, 28.5002)
  line L3 (-0.5394, 5.5002) -> (-0.5394, 28.5002)
  line L4 (-35.0394, 5.5002) -> (-0.5394, 5.5002)
  line L5 (-10.0659, 29.1) -> (-10.0659, 33.2)
  line L6 (-24.2659, 29.1) -> (-10.0659, 29.1)
  line L7 (-24.2659, 33.2) -> (-24.2659, 29.1)
  line L8 (-35.6, 33.2) -> (-24.2659, 33.2)
  line L9 (-35.6, 0) -> (-35.6, 33.2)
  line L10 (0, 0) -> (-35.6, 0)
  line L11 (0, 33.2) -> (0, 0)
  line L12 (-10.0659, 33.2) -> (0, 33.2)
  circle C1 centre (-19.5, 2) radius 0.5
  circle C2 centre (-16.5, 2) radius 0.5
  circle C3 centre (-22.5, 2) radius 0.5
  circle C4 centre (-13.5, 2) radius 0.5
  circle C5 centre (-2.5, 30.7) radius 2
  circle C6 centre (-33.1, 30.8) radius 2
  circle C7 centre (-33.1, 2.5) radius 2
  circle C8 centre (-2.5, 2.5) radius 2
  circle C9 centre (-13.5, 2) radius 0.75
  circle C10 centre (-16.5, 2) radius 0.75
  circle C11 centre (-19.5, 2) radius 0.75
  circle C12 centre (-22.5, 2) radius 0.75
  concentric C4 C9
  concentric C2 C10
  concentric C1 C11
  concentric C3 C12
  dimension "d63" diameter C9 = 1.5
  dimension "d64" diameter C10 = 1.5
  dimension "d65" diameter C11 = 1.5
  dimension "d66" diameter C12 = 1.5
extrude "Extrude16" add sketch "Sketch17" profile of C1 C2 C3 C4 C9 C10 C11 C12 along normal blind 0.1
extrude "Extrude17" cut of existing geometry blind -0.05
sketch "Sketch18" plane through (0, 0, 0) normal (0, -1, 0) x axis (1, 0, 0)
  line L1 (24.2659, 29.1) -> (24.2659, 33.2)
  line L2 (10.0659, 29.1) -> (24.2659, 29.1)
  line L3 (10.0659, 33.2) -> (10.0659, 29.1)
  line L4 (0, 33.2) -> (10.0659, 33.2)
  line L5 (0, 0) -> (0, 33.2)
  line L6 (35.6, 0) -> (0, 0)
  line L7 (35.6, 33.2) -> (35.6, 0)
  line L8 (24.2659, 33.2) -> (35.6, 33.2)
  circle C1 centre (19.5, 2) radius 0.5
  circle C2 centre (16.5, 2) radius 0.5
  circle C3 centre (22.5, 2) radius 0.5
  circle C4 centre (13.5, 2) radius 0.5
  circle C5 centre (2.5, 30.7) radius 2
  circle C6 centre (2.5, 2.5) radius 2
  circle C7 centre (33.1, 2.5) radius 2
  circle C8 centre (33.1, 30.8) radius 2
  circle C9 centre (13.5, 2) radius 0.75
  circle C10 centre (16.5, 2) radius 0.75
  circle C11 centre (19.5, 2) radius 0.75
  circle C12 centre (22.5, 2) radius 0.75
  concentric C4 C9
  concentric C2 C10
  concentric C1 C11
  concentric C3 C12
  dimension "d71" diameter C9 = 1.5
  dimension "d72" diameter C10 = 1.5
  dimension "d73" diameter C11 = 1.5
  dimension "d74" diameter C12 = 1.5
extrude "Extrude18" add sketch "Sketch18" profile of C1 C2 C3 C4 C9 C10 C11 C12 along normal blind 0.05
sketch "Sketch19" plane through (0, 3.3, 0) normal (0, 1, 0) x axis (-1, 0, 0)
  line L1 (-0.5394, 5.5002) -> (-35.0394, 5.5002)
  line L2 (-0.5394, 28.5002) -> (-0.5394, 5.5002)
  line L3 (-35.0394, 28.5002) -> (-0.5394, 28.5002)
  line L4 (-35.0394, 5.5002) -> (-35.0394, 28.5002)
  line L5 (-35.051, 28.5002) -> (-0.5394, 28.5002)
  line L6 (-35.051, 24.1002) -> (-35.051, 28.5002)
  line L7 (-0.5394, 24.1002) -> (-35.051, 24.1002)
  line L8 (-0.5394, 28.5002) -> (-0.5394, 24.1002)
  point P4 (-0.5394, 28.5002)
  point P6 (-0.5394, 28.5002)
  point P9 (-0.5394, 24.1002)
  horizontal L5
  vertical L6
  horizontal L7
  vertical L8
  coincident P4 P6
  dimension "d77" distance P6 P9 = 4.4
extrude "Extrude19" cut sketch "Sketch19" profile of L2 L3 L4 L5 L7 L8 against normal blind 0.1
component_from_bodies "Body->Comp"
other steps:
base_feature "Base Feature"
create_component "CreateComponent1"
remove_body "RemoveBody1"

design "Button_Board_II"
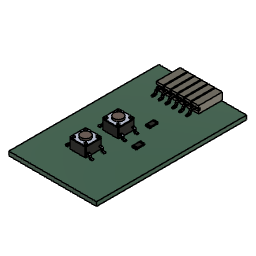
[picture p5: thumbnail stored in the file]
description: KiCad electronic assembly
part number: Button_Board_II 1
description: Part Number
part number: Ceramic
part number: Contacts
part number: Contacts (Mirror #1)
part number: Overcoat
part number: Resistor-1206
part number: Body
part number: Body001
part number: Body002
part number: Body003 (Mirror #1)
base_feature "Base Feature1"
base_feature "Base Feature1"
base_feature "Base Feature1"
base_feature "Base Feature1"
base_feature "Base Feature1"
base_feature "Base Feature1"
base_feature "Base Feature1"
base_feature "Base Feature1"
base_feature "Base Feature1"
base_feature "Base Feature1"
base_feature "Base Feature1"
base_feature "Base Feature1"
base_feature "Base Feature1"
base_feature "Base Feature1"
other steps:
create_component "CreateComponent1"
create_component "CreateComponent1"
create_component "CreateComponent2"
create_component "CreateComponent3"
create_component "CreateComponent4"
create_component "CreateComponent2"
create_component "CreateComponent1"
create_component "CreateComponent2"
create_component "CreateComponent3"
create_component "CreateComponent4"
create_component "CreateComponent5"
create_component "CreateComponent6"
create_component "CreateComponent7"
create_component "CreateComponent3"
create_component "CreateComponent1"
create_component "CreateComponent2"
create_component "CreateComponent4"

design "DB_Updated"
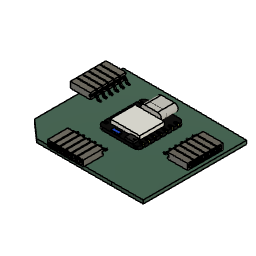
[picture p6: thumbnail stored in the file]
description: KiCad electronic assembly
part number: DB_Updated 1
description: Part Number
part number: DB_Updated 1.1.1
part number: DB_Updated 1.1.2
part number: PinSocket-01x06_P2.54mm_Horizontal_SMD
part number: SoC_nRF_Sense
part number: Mic_nRF_Sense
part number: Antenna_nRF_Sense
part number: Board
part number: USB
part number: Contact
base_feature "Base Feature1"
base_feature "Base Feature1"
base_feature "Base Feature1"
base_feature "Base Feature1"
base_feature "Base Feature1"
base_feature "Base Feature1"
base_feature "Base Feature1"
base_feature "Base Feature1"
base_feature "Base Feature1"
base_feature "Base Feature1"
base_feature "Base Feature1"
base_feature "Base Feature1"
base_feature "Base Feature1"
base_feature "Base Feature1"
base_feature "Base Feature1"
base_feature "Base Feature1"
base_feature "Base Feature1"
base_feature "Base Feature1"
base_feature "Base Feature1"
base_feature "Base Feature1"
base_feature "Base Feature1"
base_feature "Base Feature1"
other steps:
create_component "CreateComponent1"
create_component "CreateComponent1"
create_component "CreateComponent2"
create_component "CreateComponent2"
create_component "CreateComponent1"
create_component "CreateComponent2"
create_component "CreateComponent3"
create_component "CreateComponent4"
create_component "CreateComponent1"
create_component "CreateComponent2"
create_component "CreateComponent3"
create_component "CreateComponent4"
create_component "CreateComponent1"
create_component "CreateComponent2"
create_component "CreateComponent3"
create_component "CreateComponent4"
create_component "CreateComponent5"
create_component "CreateComponent6"
create_component "CreateComponent7"
create_component "CreateComponent8"
create_component "CreateComponent9"
create_component "CreateComponent10"
create_component "CreateComponent11"
create_component "CreateComponent12"
create_component "CreateComponent13"
create_component "CreateComponent3"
